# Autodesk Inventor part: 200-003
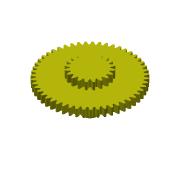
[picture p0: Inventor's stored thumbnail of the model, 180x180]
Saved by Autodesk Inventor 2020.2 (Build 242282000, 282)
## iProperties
Manager: www.cadconsulting.pl
Company: Fabian Stasiak CAD Consulting
CustomPartVersion: 1
Created: 2014-01
Part Number: 200-003
Material: Steel
Document SubType Name: Modeling
Designer: F.Stasiak
Categories: <?xml version="1.0" encoding="UTF-16"?> <MemberInstance><Categories><FamilyTemplate><FamilyTemplateParameter ValueType="xs:double" Id="1" ObjectReferenceKey="da
Density: 1 g/cm^3
Appearance: Żółta
Description: Koło 51/20
Author: F.Stasiak
Subject: Zbiór ćwiczeń. Autodesk Inventor 2020. Kurs podstawowy
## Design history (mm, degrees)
sketch "Sketch1"
  geometry: C1 r 59.067 at (0, 0)
  constraints: 1 centre point
  dimensions: "d0" = 118.13341 diameter of C1 (= da_da)
extrude "Extrusion1" new body sketch "Sketch1" distance "d1" = 10 (= da_b); taper "d2" = 0 deg
workplane "Work Plane2"
sketch "Sketch2"
  geometry: C1 r 59.067 at (0, 0) reference; C2 r 57.465 at (0, 0)
  constraints: 1 centre point, 1 coincident
  dimensions: "d3" = 114.92958 diameter of C2 (= da_dw)
feature "Średnica podziałowa" sketch "Sketch2" dims "d4" = 10, "d5" = 0
workplane "Work Plane8"
workplane "Work Plane9"
feature "Przekładnia walcowa" dims "d34" = 0.616 (computed from da_z), "da_b" = 10, "da_d" = 114.75, "da_aw" = 80, "da_da" = 118.13341, "da_df" = 108.00988, "da_dw" = 114.92958, angle "da_beta" = 0 deg, "da_lefttooth" = 0, "da_righttooth" = 0
node "Przekładnia walcowa1" dims "d53" = 10
feature "Przesuń bryłę2"
sketch "Szkic3"
  geometry: C1 r 10 at (0, 0); A1 r 54.005 centre (0, 0) between (10.74, 52.926) and (9.105, 53.232) reference
  constraints: 1 centre point, 1 coincident
  dimensions: "d57" = 20 diameter of C1
extrude "Wyciągnięcie proste2" join sketch "Szkic3" distance "d58" = 35; taper "d59" = 0 deg
body "Solid1"
body "Srf1"
feature "Solid1::Przekładnia walcowa1" dims "d53" = 10
tag "Bryła wyprowadzona2"
node "Bryła3"
other parameters: "d17" = 0, "d39" = 0, "d41" = 0, "d47" = 0, "d48" = 0, "d54" = 0, "d55" = 0
